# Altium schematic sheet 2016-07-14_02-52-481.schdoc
size 387 x 177 mm; SheetNumber: 1; SheetTotal: 1
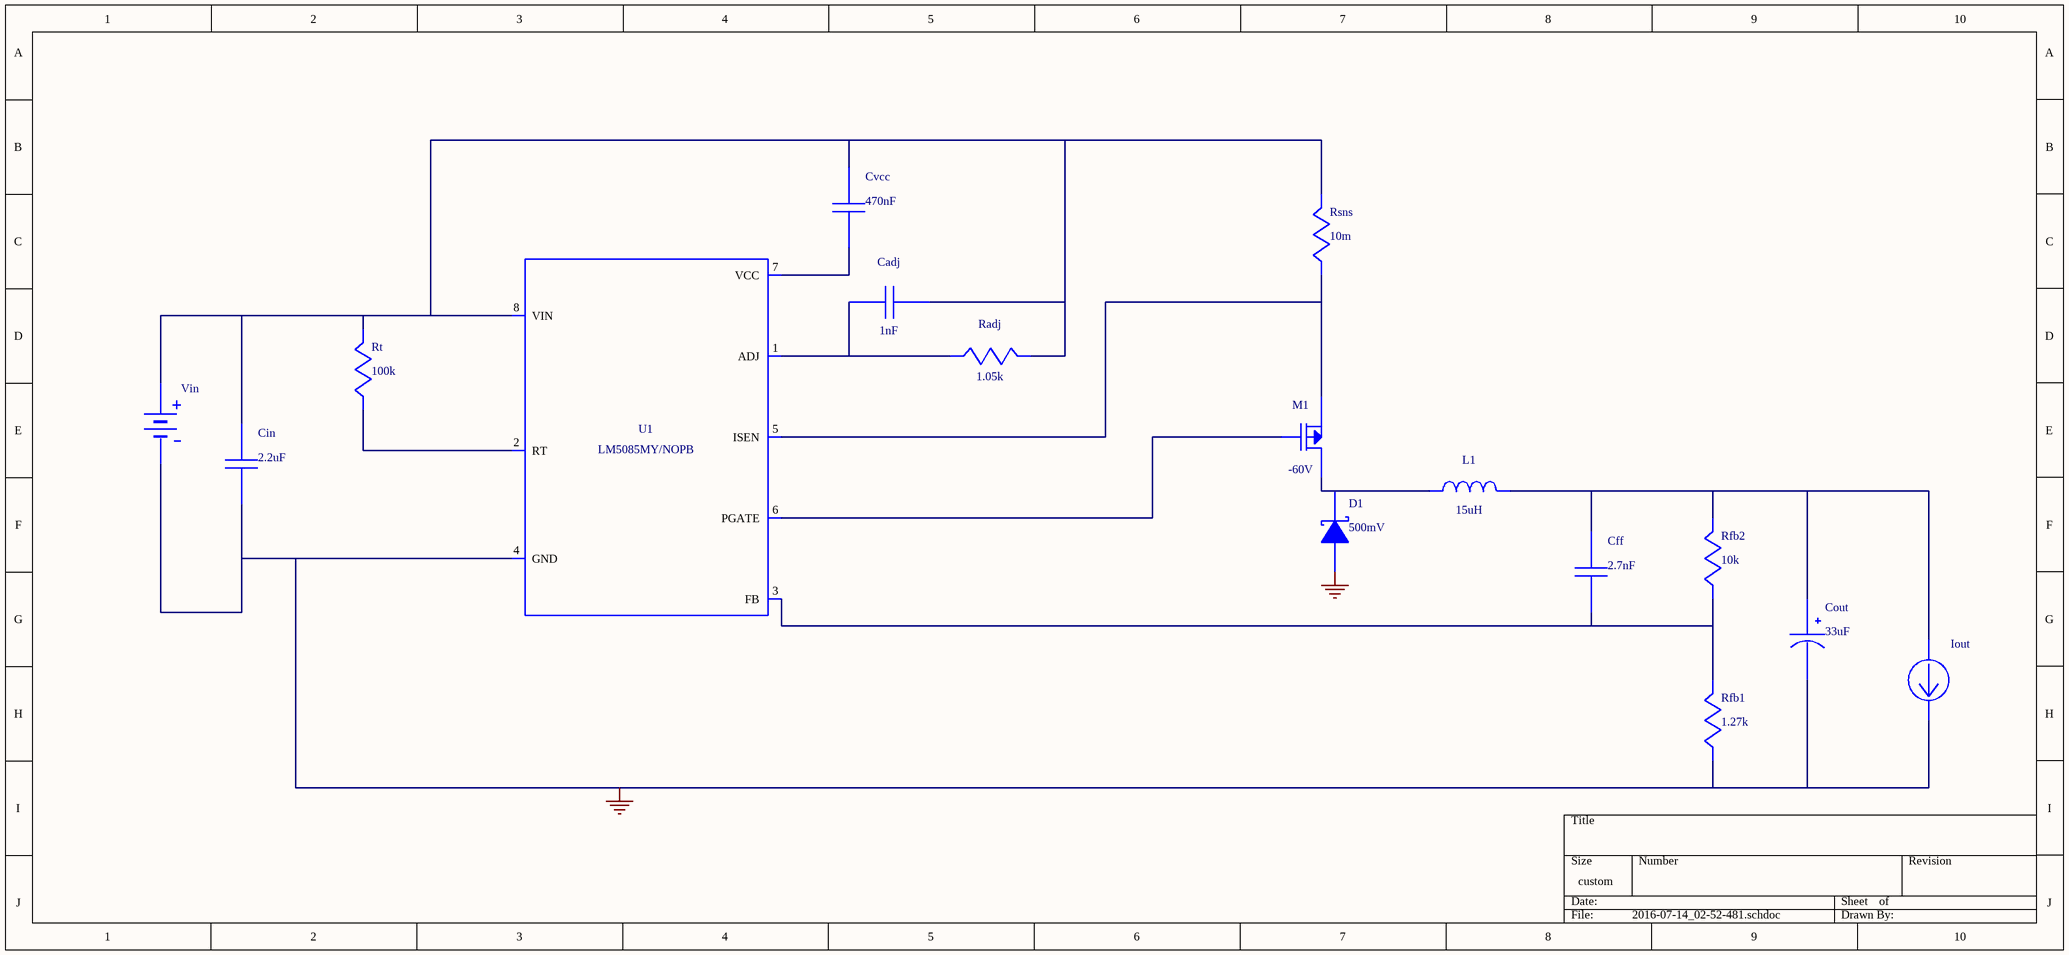
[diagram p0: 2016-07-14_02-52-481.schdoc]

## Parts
Cadj  value 1nF  (hidden comment: CL21C102JBCNFNC)
Cff  value 2.7nF  (hidden comment: 08053A272JAT2A)
Cin  value 2.2uF  (hidden comment: GRM31CR71H225KA88L)
Cout  value 33uF  (hidden comment: TPSC336K020R0300)
Cvcc  value 470nF  (hidden comment: 0805YC474KAT2A)
D1  value 500mV  (hidden comment: B240A-13-F)
Iout  WB_CURRENT_LOAD  (value not drawn)
L1  value 15uH  (hidden comment: CLF10040T-150M)
M1  value -60V  (hidden comment: FDC5614P)
Radj  value 1.05k  (hidden comment: CRCW04021K05FKED)
Rfb1  value 1.27k  (hidden comment: CRCW04021K27FKED)
Rfb2  value 10k  (hidden comment: CRCW040210K0FKED)
Rsns  value 10m  (hidden comment: CSR1206FK10L0)
Rt  value 100k  (hidden comment: CRCW0402100KFKED)
U1  LM5085MY/NOPB
Vin  WB_BATTERY  (value not drawn)

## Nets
0: Cin.2 Cout.2(-) D1.2(A) Iout.2(-) Rfb1.2 U1.4(GND) U1.9(EP) Vin.2(-)
NetCadj_1: Cadj.1 Cin.1 Cvcc.1 Radj.1 Rsns.1 Rt.1 U1.8(VIN) Vin.1(+)
NetCadj_2: Cadj.2 Radj.2 U1.1(ADJ)
NetCff_1: Cff.1 Cout.1(+) Iout.1(+) L1.2 Rfb2.1
NetCff_2: Cff.2 Rfb1.1 Rfb2.2 U1.3(FB)
NetCvcc_2: Cvcc.2 U1.7(VCC)
NetD1_1: D1.1(K) L1.1 M1.1(Drain) M1.2(Drain) M1.5(Drain) M1.6(Drain)
NetM1_3: M1.3(Gate) U1.6(PGATE)
NetM1_4: M1.4(Source) Rsns.2 U1.5(ISEN)
NetRt_2: Rt.2 U1.2(RT)

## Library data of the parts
Cadj = CL21C102JBCNFNC: Manufacturer Name: Samsung Electro-Mechanics
Cff = 08053A272JAT2A: Manufacturer Name: AVX
Cin = GRM31CR71H225KA88L: GRM31CR71H225KA8; Manufacturer Name: MuRata
Cout = TPSC336K020R0300: Manufacturer Name: AVX
Cvcc = 0805YC474KAT2A: Manufacturer Name: AVX
D1 = B240A-13-F: Manufacturer Name: Diodes Inc.
L1 = CLF10040T-150M: Unknown; Manufacturer Name: TDK
M1 = FDC5614P: Manufacturer Name: Fairchild Semiconductor
Radj = CRCW04021K05FKED: Manufacturer Name: Vishay-Dale
Rfb1 = CRCW04021K27FKED: Manufacturer Name: Vishay-Dale
Rfb2 = CRCW040210K0FKED: Manufacturer Name: Vishay-Dale
Rsns = CSR1206FK10L0: Manufacturer Name: Stackpole Electronics Inc
Rt = CRCW0402100KFKED: Manufacturer Name: Vishay-Dale
U1 = LM5085MY/NOPB: Manufacturer Name: Texas Instruments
